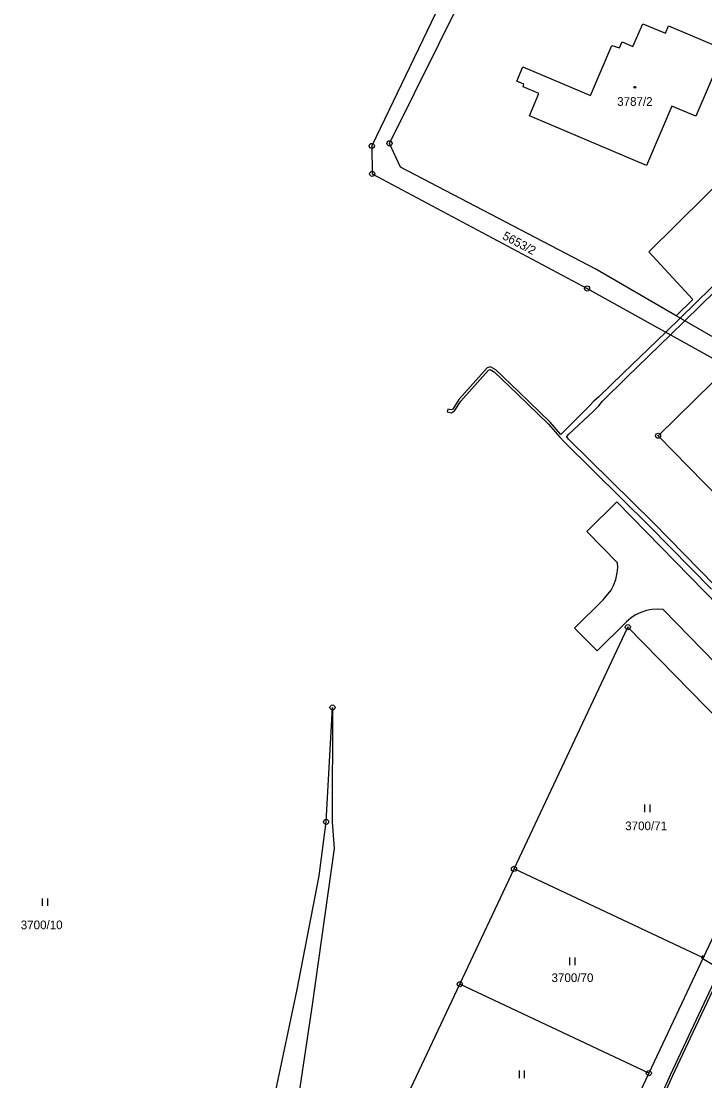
# Model space of a CAD drawing. Extents: x -644096 to -634268, y -1141430 to -1133463.
# Drawn here: x -641189.1 to -641055, y -1137646.2 to -1137438.3 of the extents above; entities that cross this region are included whole.
import ezdxf

# ---------------------------------------------------------------- set-up
doc = ezdxf.new("R2010")
doc.units = 0
for name, color, linetype in [('_CIVIL_CONSTRUCTION', 7, 'Continuous'), ('B_Hranice _3D', 7, 'Continuous'), ('M_Svah_Zarez', 7, 'Continuous'), ('svrsek_osa_sjezdy', 7, 'Continuous'), ('svrsek_osa_VRT', 7, 'Continuous'), ('terminal_VRT', 7, 'Continuous')]:
    doc.layers.add(name, color=color, linetype=linetype)

msp = doc.modelspace()

# ---------------------------------------------------------------- linework, layer by layer
at = {"layer": '_CIVIL_CONSTRUCTION'}
for centre, radius in [((-641120.37, -1137462.82), 0.5), ((-641120.37, -1137462.82), 0.0303), ((-641116.89, -1137462.31), 0.5), ((-641116.89, -1137462.31), 0.0303), ((-641120.29, -1137468.29), 0.5), ((-641120.29, -1137468.29), 0.0303), ((-641078.13, -1137490.78), 0.5), ((-641078.13, -1137490.78), 0.0303), ((-641064.21, -1137519.67), 0.5), ((-641064.21, -1137519.67), 0.0303), ((-641070.14, -1137557.23), 0.5), ((-641070.14, -1137557.23), 0.0303), ((-641128.08, -1137573), 0.5), ((-641128.08, -1137573), 0.0303), ((-641129.34, -1137595.43), 0.5), ((-641129.34, -1137595.43), 0.0303), ((-641092.47, -1137604.66), 0.5), ((-641092.47, -1137604.66), 0.0303), ((-641103.12, -1137627.28), 0.5), ((-641103.12, -1137627.28), 0.0303), ((-641066.02, -1137644.74), 0.5), ((-641066.02, -1137644.74), 0.0303)]:
    msp.add_circle(centre, radius, dxfattribs=at)
at = {"layer": 'B_Hranice _3D'}
for points in [[(-641050.81, -1137487.74), (-641059.87, -1137496.59), (-641062.7, -1137499.36), (-641071.12, -1137507.47), (-641075.8, -1137512.07), (-641076.78, -1137512.92), (-641077.79, -1137513.95), (-641082.91, -1137519.04), (-641083.27, -1137519.43), (-641085.38, -1137517.02), (-641091.46, -1137511.14), (-641096.04, -1137506.74), (-641097.06, -1137506.13), (-641097.76, -1137506.35), (-641103.31, -1137512.57), (-641104.5, -1137514.44), (-641104.81, -1137514.62), (-641105.47, -1137514.49), (-641105.57, -1137514.97), (-641104.73, -1137515.16), (-641104.14, -1137514.8), (-641102.91, -1137512.87), (-641097.48, -1137506.79), (-641097.12, -1137506.67), (-641096.34, -1137507.14), (-641091.8, -1137511.5), (-641085.74, -1137517.36), (-641083.45, -1137519.98), (-641082.53, -1137521.01), (-641065.92, -1137537.42), (-641053.74, -1137549.8)], [(-641053.02, -1137549.1), (-641065.19, -1137536.73), (-641081.77, -1137520.37), (-641082.09, -1137519.9), (-641082.09, -1137519.82), (-641081.71, -1137519.35), (-641076.92, -1137514.9), (-641075.84, -1137513.78), (-641075.12, -1137512.9), (-641070.35, -1137508.2), (-641061.79, -1137499.87), (-641058.97, -1137497.11), (-641050.09, -1137488.44)], [(-641055.02, -1137621.94), (-641055.24, -1137621.84), (-641055.49, -1137621.73), (-641055.61, -1137622.01), (-641055.69, -1137622.19), (-641055.45, -1137622.29), (-641055.24, -1137622.38), (-641052.17, -1137624.22)], [(-641052.75, -1137625.8), (-641057.25, -1137635.38), (-641061.81, -1137645.14), (-641066.23, -1137654.96)], [(-641065.77, -1137655.16), (-641061.35, -1137645.34), (-641056.79, -1137635.6), (-641052.29, -1137626.02)]]:
    msp.add_lwpolyline(points, dxfattribs=at)
at = {"layer": 'M_Svah_Zarez'}
msp.add_circle((-641068.77, -1137451.31), 0.175, dxfattribs=at)
at = {"layer": 'svrsek_osa_sjezdy'}
for p, q in [((-641066.79, -1137593.53), (-641066.79, -1137592.03)), ((-641065.79, -1137593.53), (-641065.79, -1137592.03)), ((-641184.95, -1137611.94), (-641184.95, -1137610.44)), ((-641183.95, -1137611.94), (-641183.95, -1137610.44)), ((-641081.5, -1137623.54), (-641081.5, -1137622.04)), ((-641080.5, -1137623.54), (-641080.5, -1137622.04)), ((-641091.4, -1137645.7), (-641091.4, -1137644.2)), ((-641090.4, -1137645.7), (-641090.4, -1137644.2))]:
    msp.add_line(p, q, dxfattribs=at)
at = {"layer": 'terminal_VRT'}
for p, q in [((-641047.78, -1137503.56), (-641060.64, -1137496.14)), ((-641042.17, -1137594.07), (-641055.37, -1137622.12)), ((-641103.12, -1137627.28), (-641092.47, -1137604.66)), ((-641055.37, -1137622.12), (-641092.47, -1137604.66)), ((-641055.37, -1137622.12), (-641066.02, -1137644.74)), ((-641113.76, -1137649.9), (-641103.12, -1137627.28)), ((-641066.02, -1137644.74), (-641103.12, -1137627.28)), ((-641066.02, -1137644.74), (-641076.67, -1137667.36))]:
    msp.add_line(p, q, dxfattribs=at)
for points in [[(-641060.64, -1137496.14), (-641076.45, -1137486.99), (-641114.77, -1137466.97), (-641116.89, -1137462.31), (-641102.24, -1137432.78), (-641097.33, -1137422.91)], [(-641106.08, -1137426.32), (-641105.4, -1137431.59), (-641120.37, -1137462.82), (-641120.29, -1137468.29), (-641078.13, -1137490.78), (-641050.44, -1137506.18)], [(-641066.47, -1137466.68), (-641089.46, -1137456.91), (-641087.57, -1137452.52), (-641090.69, -1137451.19), (-641090.54, -1137450.72), (-641091.93, -1137450.08), (-641090.75, -1137447.32), (-641077.48, -1137452.94), (-641073.25, -1137443.11), (-641071.78, -1137443.58), (-641071.27, -1137442.42), (-641069.16, -1137443.33), (-641067.22, -1137438.86), (-641062.76, -1137440.72), (-641062.13, -1137439.26), (-641051.18, -1137443.88), (-641056.79, -1137456.98), (-641061.5, -1137455.03), (-641066.47, -1137466.68)], [(-641035.2, -1137453.14), (-641043.95, -1137461.77), (-641066.05, -1137483.59), (-641057.42, -1137492.96), (-641060.64, -1137496.14)], [(-641043.07, -1137541.29), (-641064.21, -1137519.67), (-641053.49, -1137509.18)], [(-641034.98, -1137582.71), (-641063.23, -1137553.78), (-641064.32, -1137553.7), (-641065.41, -1137553.76), (-641066.45, -1137553.99), (-641067.62, -1137554.38), (-641068.61, -1137554.84), (-641069.46, -1137555.41), (-641070.39, -1137556.22), (-641076.18, -1137561.88), (-641080.59, -1137557.41), (-641074.95, -1137551.85), (-641073.42, -1137549.97), (-641072.94, -1137549.03), (-641072.52, -1137547.87), (-641072.26, -1137546.57), (-641072.11, -1137545.53), (-641072.18, -1137544.61), (-641078.21, -1137538.46), (-641072.28, -1137532.63), (-641032.15, -1137573.71)], [(-641092.47, -1137604.66), (-641070.14, -1137557.23), (-641039.55, -1137588.5), (-641042.17, -1137594.07)], [(-641122.04, -1137667.48), (-641137.96, -1137662.12), (-641139.92, -1137661.73), (-641139.24, -1137648.49), (-641134.98, -1137628.34), (-641130.71, -1137606.01), (-641129.34, -1137595.43), (-641128.08, -1137573), (-641128.15, -1137595.5), (-641127.77, -1137600.67), (-641132.16, -1137631.8), (-641135.73, -1137655.84), (-641122.09, -1137662.38), (-641119.95, -1137663.05)]]:
    msp.add_lwpolyline(points, dxfattribs=at)

# ---------------------------------------------------------------- texts
at = {"layer": 'svrsek_osa_VRT'}
for s, p in [('3787/2', (-641072.23, -1137454.95)), ('3700/71', (-641070.66, -1137597.07)), ('3700/10', (-641189.24, -1137616.5)), ('3700/70', (-641085.11, -1137626.86))]:
    msp.add_text(s, height=1.7, dxfattribs=at).set_placement(p)
msp.add_text('5653/2', height=1.7, rotation=332, dxfattribs=at).set_placement((-641094.9, -1137481))

doc.saveas('drawing.dxf')
